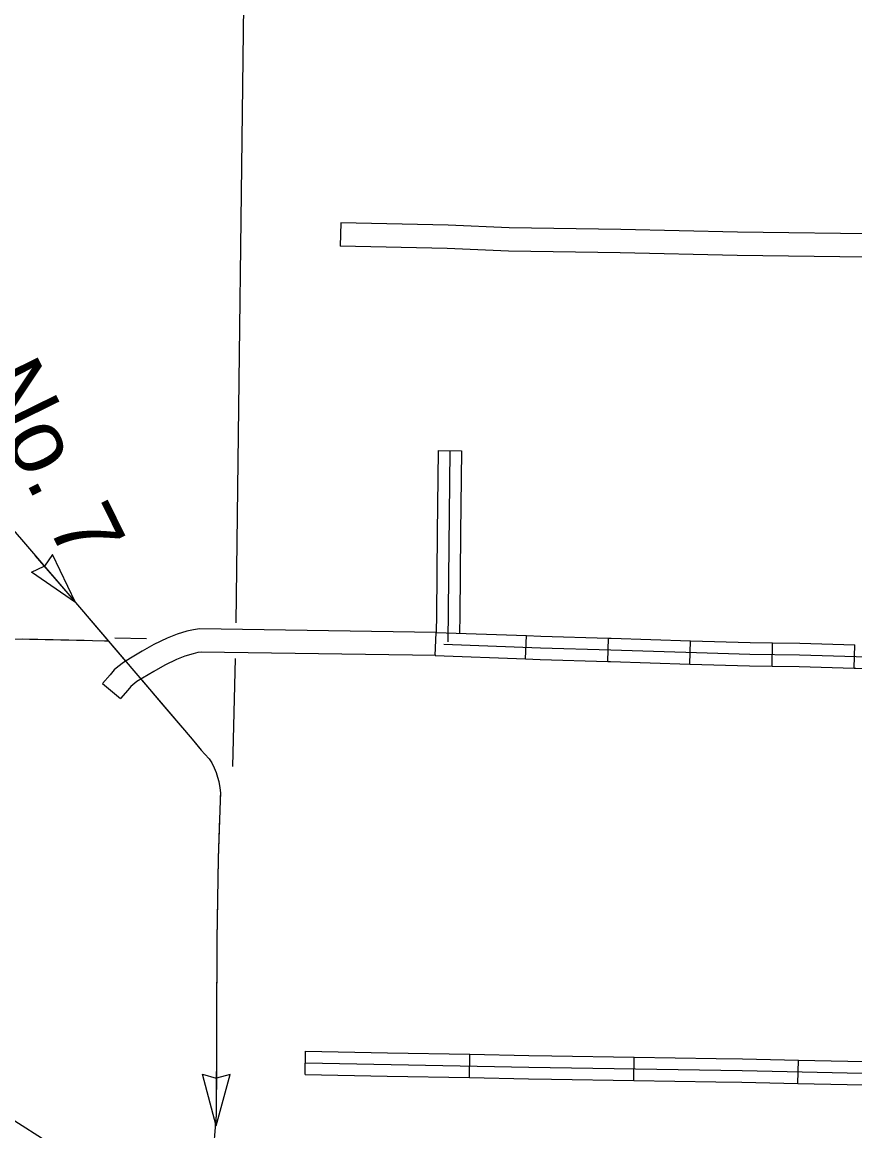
# Model space of a CAD drawing. Extents: x 1196286 to 1268366, y 2040822 to 2082115.
# Drawn here: x 1221760 to 1223766, y 2058695 to 2061367 of the extents above; entities that cross this region are included whole.
import ezdxf

# ---------------------------------------------------------------- set-up
doc = ezdxf.new("R2010")
doc.units = 0
for name, color, linetype in [('60', 7, 'Continuous'), ('61', 7, 'Continuous'), ('62', 7, 'Continuous'), ('63', 7, 'Continuous'), ('Level 69', 7, 'Continuous'), ('Level 72', 7, 'Continuous')]:
    doc.layers.add(name, color=color, linetype=linetype)

msp = doc.modelspace()

# ---------------------------------------------------------------- linework, layer by layer
at = {"layer": '60'}
for points in [[(1222294.8, 2061538.3), (1222274.9, 2059919.6)], [(1222059.4, 2059881.2), (1221983.2, 2059882.3)], [(1222273.2, 2059833.3), (1222266.5, 2059573.5)]]:
    msp.add_lwpolyline(points, dxfattribs=at)
at = {"layer": '61'}
for p, q in [((1222755.4, 2059840.4), (1222757.6, 2059896.6)), ((1222972.8, 2059832.4), (1222975, 2059888.6)), ((1223171.1, 2059826.6), (1223172.6, 2059882.8)), ((1223368.8, 2059820.2), (1223370.6, 2059876.4)), ((1223567.3, 2059814.8), (1223568, 2059871.1)), ((1223764.9, 2059810.5), (1223766.3, 2059866.7))]:
    msp.add_line(p, q, dxfattribs=at)
for points in [[(1222757.6, 2059896.6), (1222975, 2059888.6)], [(1222975, 2059888.6), (1223009.8, 2059887.2), (1223172.6, 2059882.8)], [(1222776.1, 2059868.2), (1223008.9, 2059859.1), (1223178.6, 2059854.5), (1223513.3, 2059843.7), (1223633, 2059842.1), (1223769.6, 2059838.5), (1223816.4, 2059836.4), (1223847.5, 2059833.8), (1224000.8, 2059824.1), (1224081, 2059819.5), (1224106.9, 2059818.7), (1224129.2, 2059818.7)], [(1223172.6, 2059882.8), (1223179.5, 2059882.6), (1223370.6, 2059876.4)], [(1223370.6, 2059876.4), (1223513.9, 2059871.8), (1223568, 2059871.1)], [(1223568, 2059871.1), (1223633.5, 2059870.2), (1223766.3, 2059866.7)], [(1222755.4, 2059840.4), (1222972.8, 2059832.4)], [(1222972.8, 2059832.4), (1223007.9, 2059831), (1223171.1, 2059826.6)], [(1223171.1, 2059826.6), (1223177.8, 2059826.4), (1223368.8, 2059820.2)], [(1223368.8, 2059820.2), (1223512.6, 2059815.6), (1223567.3, 2059814.8)], [(1223567.3, 2059814.8), (1223632.4, 2059814), (1223764.9, 2059810.5)], [(1223764.9, 2059810.5), (1223768.7, 2059810.4), (1223814.5, 2059808.4), (1223845.4, 2059805.7), (1223961.4, 2059798.4)]]:
    msp.add_lwpolyline(points, dxfattribs=at)
at = {"layer": '63'}
for p, q in [((1221832.8, 2060084.5), (1221813.5, 2060056.3)), ((1221888.3, 2059968.4), (1221832.8, 2060084.5)), ((1221782.2, 2060041.3), (1221813.1, 2060056)), ((1221888.3, 2059968.4), (1221782.2, 2060041.3)), ((1222227.3, 2058706.9), (1222194.4, 2058831.3)), ((1222194.4, 2058831.3), (1222227.5, 2058822.3)), ((1222227.3, 2058706.9), (1222261.1, 2058831)), ((1222261.1, 2058831), (1222227.9, 2058822.3))]:
    msp.add_line(p, q, dxfattribs=at)
for points in [[(1221635, 2060262.3), (1221869.7, 2059990.1), (1222169.7, 2059639.2), (1222191.1, 2059612.6), (1222199.9, 2059603), (1222210.2, 2059591.7), (1222217, 2059581.7), (1222222.6, 2059570.1), (1222227.3, 2059559.1), (1222230.4, 2059547.2), (1222233.5, 2059536.8), (1222236, 2059521.8), (1222237.5, 2059509.4), (1222236.7, 2059490.9), (1222232.3, 2059351.8), (1222228.9, 2059156.2), (1222227.4, 2058732.8), (1222218.8, 2058625.5)], [(1221791.4, 2060081), (1221869.7, 2059990.1), (1221888.3, 2059968.4)], [(1220850, 2059920.6), (1220884.7, 2059902.1), (1220902.7, 2059898.8), (1221967.1, 2059876.2)], [(1221920.5, 2059930.8), (1221967.1, 2059876.2), (1222008.8, 2059827.5)], [(1221760.7, 2059880.6), (1221909.2, 2059877.4)], [(1221958.6, 2059876.4), (1221967.1, 2059876.2)], [(1222049.1, 2059780.3), (1222097.3, 2059723.8)], [(1222097.3, 2059723.8), (1222145.6, 2059667.4)], [(1222177.5, 2059629.5), (1222191.1, 2059612.6), (1222199.9, 2059603), (1222210.2, 2059591.7), (1222217, 2059581.7), (1222222.6, 2059570.1), (1222227.3, 2059559.1), (1222230.4, 2059547.2), (1222233.5, 2059536.8), (1222236, 2059521.8), (1222237.5, 2059509.4), (1222237, 2059498.7)], [(1222235.4, 2059449.3), (1222232.3, 2059351.8), (1222231.4, 2059300.8)], [(1222230.6, 2059251.3), (1222228.9, 2059156.2), (1222228.7, 2059102.9)], [(1222228.5, 2059053.4), (1222228, 2058904.9)], [(1221306.2, 2058996.8), (1221797.5, 2058683.7), (1221815.9, 2058671.7), (1221824.2, 2058665.4), (1221829.9, 2058658.3), (1221835.5, 2058649.4), (1221844.5, 2058637), (1221894, 2058531), (1222099.7, 2058122.8), (1222205.3, 2057914.4)], [(1222227.8, 2058855.4), (1222227.4, 2058732.8), (1222225.3, 2058706.9)]]:
    msp.add_lwpolyline(points, dxfattribs=at)
at = {"layer": 'Level 69'}
for p, q in [((1222762.5, 2060334.6), (1222818.7, 2060334)), ((1222790.6, 2060334.3), (1222785.4, 2059873.5)), ((1222441.5, 2058830.9), (1222442.6, 2058887.1)), ((1222837.5, 2058823.2), (1222838.5, 2058879.5)), ((1223233.5, 2058816.3), (1223234.4, 2058872.6)), ((1223629.3, 2058809.1), (1223630.5, 2058865.4))]:
    msp.add_line(p, q, dxfattribs=at)
for points in [[(1222762.5, 2060334.6), (1222760.3, 2060136.6)], [(1222818.7, 2060334), (1222816.5, 2060136)], [(1222760.3, 2060136.6), (1222758, 2059938.7)], [(1222816.5, 2060136), (1222814.3, 2059938)], [(1222758, 2059938.7), (1222757.6, 2059896.6)], [(1222814.3, 2059938), (1222813.8, 2059894.9)], [(1222442.6, 2058887.1), (1222640.6, 2058883.3)], [(1222640.6, 2058883.3), (1222838.5, 2058879.5)], [(1222838.5, 2058879.5), (1222980.9, 2058876.7), (1223036.4, 2058875.8)], [(1223036.4, 2058875.8), (1223234.4, 2058872.6)], [(1223234.4, 2058872.6), (1223432.4, 2058869.3)], [(1222442.1, 2058859), (1222980.4, 2058848.6), (1223494.8, 2058840.2), (1223892.2, 2058831.6), (1224173.4, 2058826.6)], [(1223432.4, 2058869.3), (1223495.4, 2058868.3), (1223630.5, 2058865.4)], [(1223630.5, 2058865.4), (1223828.4, 2058861.1)], [(1222441.5, 2058830.9), (1222639.5, 2058827.1)], [(1222639.5, 2058827.1), (1222837.5, 2058823.2)], [(1222837.5, 2058823.2), (1222979.9, 2058820.5), (1223035.5, 2058819.5)], [(1223035.5, 2058819.5), (1223233.5, 2058816.3)], [(1223233.5, 2058816.3), (1223431.5, 2058813.1)], [(1223431.5, 2058813.1), (1223494.3, 2058812.1), (1223629.3, 2058809.1)], [(1223629.3, 2058809.1), (1223827.2, 2058804.9)]]:
    msp.add_lwpolyline(points, dxfattribs=at)
at = {"layer": 'Level 72'}
for points in [[(1223919.2, 2060854.2), (1223855.4, 2060856.6), (1223483.6, 2060861.1), (1223202.2, 2060867.6), (1222933.8, 2060871.5), (1222786.2, 2060877.9), (1222527.6, 2060884), (1222526.3, 2060827.7)], [(1223914.6, 2060798.1), (1223854, 2060800.3), (1223482.6, 2060804.9), (1223201.2, 2060811.4), (1222932.2, 2060815.3), (1222784.3, 2060821.6), (1222526.3, 2060827.7)], [(1222757.6, 2059896.6), (1222187, 2059905.3), (1222172.6, 2059903), (1222156.9, 2059899.3), (1222133, 2059892), (1222109.3, 2059882.7), (1222077.1, 2059867), (1222049.4, 2059851.3), (1222020.6, 2059834.4), (1222004.2, 2059824.3), (1221990.4, 2059813.5), (1221981.8, 2059805.9), (1221971.6, 2059794.4), (1221953.8, 2059773.4), (1221996.8, 2059737.1)], [(1222756.9, 2059840.4), (1222191.1, 2059849), (1222183.4, 2059847.8), (1222171.6, 2059845), (1222151.5, 2059838.8), (1222131.9, 2059831.2), (1222103.3, 2059817.2), (1222077.5, 2059802.6), (1222049.6, 2059786.2), (1222036.4, 2059778.1), (1222026.5, 2059770.3), (1222021.7, 2059766), (1222014.1, 2059757.6), (1221996.8, 2059737.1)]]:
    msp.add_lwpolyline(points, dxfattribs=at)

# ---------------------------------------------------------------- texts
at = {"layer": '62'}
msp.add_text('No. 7', height=158.4, rotation=296.2043, dxfattribs=at).set_placement((1221647.6, 2060504.7))

doc.saveas('drawing.dxf')
